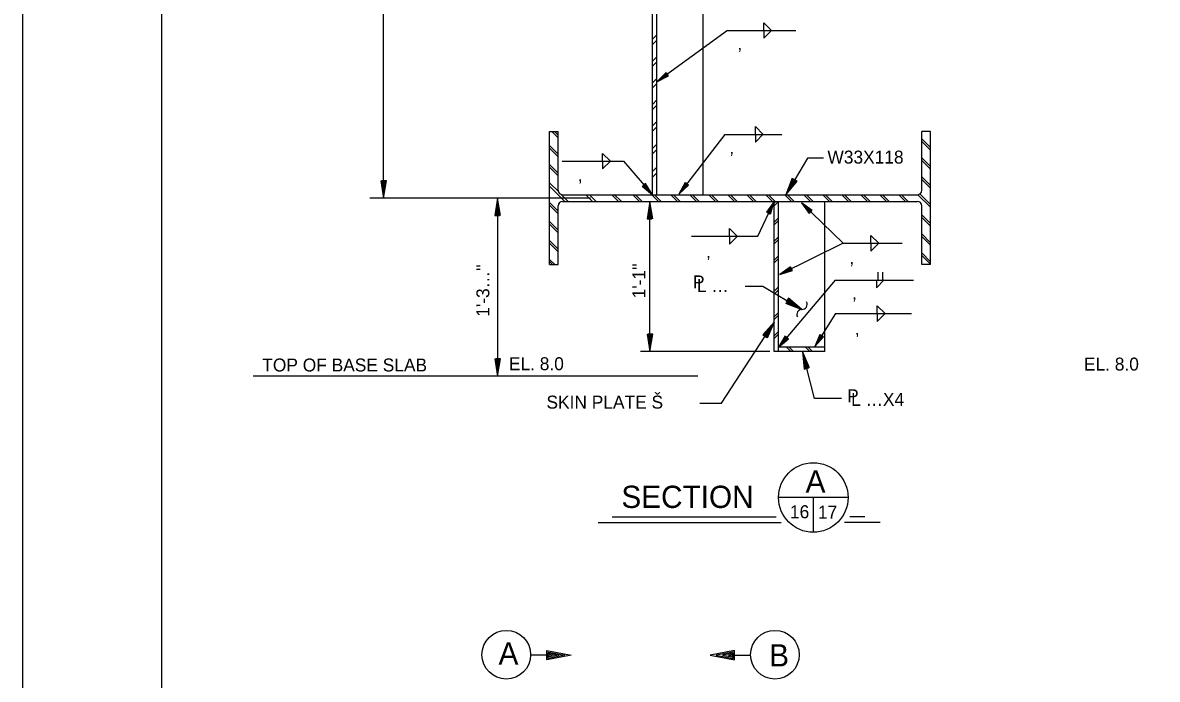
# Model space of a CAD drawing. Extents: x 4.9 to 31.6, y 3.9 to 22.6.
# Drawn here: x 4.91 to 13.07, y 13.34 to 18.06 of the extents above; entities that cross this region are included whole.
import ezdxf

# ---------------------------------------------------------------- set-up
doc = ezdxf.new("R2010")
doc.units = 0
for name, color, linetype in [('Level 1', 7, 'Continuous'), ('Level 10', 7, 'Continuous'), ('Level 2', 7, 'Continuous'), ('Level 25', 7, 'Continuous'), ('Level 3', 7, 'Continuous'), ('Level 44', 7, 'Continuous'), ('Level 50', 7, 'Continuous')]:
    doc.layers.add(name, color=color, linetype=linetype)

msp = doc.modelspace()

# ---------------------------------------------------------------- linework, layer by layer
at = {"layer": 'Level 1'}
for points in [[(4.9069, 22.5927), (31.5735, 22.5927), (31.5735, 3.926), (4.9069, 3.926)], [(5.9069, 22.2594), (31.2402, 22.2594), (31.2402, 4.2594), (5.9069, 4.2594)]]:
    msp.add_lwpolyline(points, close=True, dxfattribs=at)
at = {"layer": 'Level 10'}
for p, q in [((9.4366, 17.9451), (9.4679, 17.9763)), ((9.4366, 17.9074), (9.4679, 17.9386)), ((9.4366, 17.7878), (9.4679, 17.819)), ((9.4366, 17.7501), (9.4679, 17.7813)), ((9.4366, 17.6322), (9.4679, 17.6634)), ((9.4366, 17.5945), (9.4679, 17.6257)), ((9.4366, 17.4766), (9.4679, 17.5079)), ((9.4366, 17.4389), (9.4679, 17.4702)), ((9.4366, 17.3211), (9.4679, 17.3523)), ((9.4366, 17.2834), (9.4679, 17.3146)), ((9.4366, 17.16), (9.4679, 17.1912)), ((9.4366, 17.1208), (9.4679, 17.1521)), ((9.4366, 16.9941), (9.4679, 17.0254)), ((9.4366, 16.9523), (9.4679, 16.9835))]:
    msp.add_line(p, q, dxfattribs=at)
at = {"layer": 'Level 2'}
for p, q in [((9.8012, 16.8271), (9.8012, 20.7144)), ((9.4366, 16.8271), (9.4366, 20.5113)), ((9.4679, 16.8271), (9.4679, 20.5113)), ((8.697, 17.2821), (8.7595, 17.2821)), ((8.697, 16.3238), (8.697, 17.2821)), ((8.7595, 17.2367), (8.7141, 17.2821)), ((8.7595, 17.2555), (8.7329, 17.2821)), ((8.7595, 16.8584), (8.7595, 17.2821)), ((11.4366, 17.2821), (11.3741, 17.2821)), ((11.3741, 16.8584), (11.3741, 17.2821)), ((11.4366, 17.1654), (11.3741, 17.2279)), ((11.4366, 16.3238), (11.4366, 17.2821)), ((8.7595, 17.1188), (8.697, 17.1813)), ((8.7595, 17.0999), (8.697, 17.1624)), ((11.4366, 17.1466), (11.3741, 17.2091)), ((11.4366, 17.0287), (11.3741, 17.0912)), ((11.4366, 17.0099), (11.3741, 17.0724)), ((8.7595, 16.9821), (8.697, 17.0446)), ((8.7595, 16.9632), (8.697, 17.0257)), ((8.761, 16.8488), (8.697, 16.9128)), ((11.4366, 16.8921), (11.3741, 16.9546)), ((11.4366, 16.8732), (11.3741, 16.9357)), ((8.8075, 16.7786), (8.697, 16.889)), ((8.831, 16.7788), (8.7812, 16.8286)), ((8.7908, 16.8271), (11.3429, 16.8271)), ((9.0058, 16.7788), (8.9575, 16.8271)), ((9.0326, 16.7788), (8.9843, 16.8271)), ((9.1932, 16.7788), (9.1449, 16.8271)), ((9.211, 16.7801), (9.1627, 16.8284)), ((9.3437, 16.7788), (9.2954, 16.8271)), ((9.3625, 16.7788), (9.3142, 16.8271)), ((9.4804, 16.7788), (9.4321, 16.8271)), ((9.4993, 16.7788), (9.4509, 16.8271)), ((9.6171, 16.7788), (9.5688, 16.8271)), ((9.636, 16.7788), (9.5876, 16.8271)), ((9.7538, 16.7788), (9.7055, 16.8271)), ((9.7727, 16.7788), (9.7243, 16.8271)), ((9.8905, 16.7788), (9.8422, 16.8271)), ((9.9094, 16.7788), (9.861, 16.8271)), ((10.0272, 16.7788), (9.9789, 16.8271)), ((10.0461, 16.7788), (9.9978, 16.8271)), ((10.1639, 16.7788), (10.1156, 16.8271)), ((10.1828, 16.7788), (10.1345, 16.8271)), ((10.3006, 16.7788), (10.2523, 16.8271)), ((10.3195, 16.7788), (10.2712, 16.8271)), ((10.4374, 16.7788), (10.389, 16.8271)), ((10.4562, 16.7788), (10.4079, 16.8271)), ((10.5741, 16.7788), (10.5257, 16.8271)), ((10.5929, 16.7788), (10.5446, 16.8271)), ((10.7108, 16.7788), (10.6624, 16.8271)), ((10.7296, 16.7788), (10.6813, 16.8271)), ((10.8475, 16.7788), (10.7991, 16.8271)), ((10.8663, 16.7788), (10.818, 16.8271)), ((10.9842, 16.7788), (10.9359, 16.8271)), ((11.003, 16.7788), (10.9547, 16.8271)), ((11.1209, 16.7788), (11.0726, 16.8271)), ((11.1398, 16.7788), (11.0914, 16.8271)), ((11.2576, 16.7788), (11.2093, 16.8271)), ((11.2765, 16.7788), (11.2281, 16.8271)), ((11.4366, 16.7365), (11.346, 16.8271)), ((11.4366, 16.7553), (11.3598, 16.8321)), ((8.7595, 16.7087), (8.697, 16.7712)), ((8.7595, 16.6898), (8.697, 16.7523)), ((8.7595, 16.3238), (8.7595, 16.7475)), ((8.7908, 16.7788), (11.3429, 16.7788)), ((10.3116, 15.6988), (10.3116, 16.7788)), ((10.3429, 15.6988), (10.3429, 16.7788)), ((10.6762, 15.6988), (10.6762, 16.7788)), ((11.3741, 16.3238), (11.3741, 16.7475)), ((11.4366, 16.6186), (11.3741, 16.6811)), ((11.4366, 16.5998), (11.3741, 16.6623)), ((8.7595, 16.572), (8.697, 16.6345)), ((8.7595, 16.5531), (8.697, 16.6156)), ((8.7595, 16.4353), (8.697, 16.4978)), ((11.4366, 16.4819), (11.3741, 16.5444)), ((11.4366, 16.4631), (11.3741, 16.5256)), ((8.7595, 16.4164), (8.697, 16.4789)), ((11.4366, 16.3452), (11.3741, 16.4077)), ((8.7344, 16.3238), (8.697, 16.3612)), ((8.7189, 16.3238), (8.697, 16.3457)), ((8.697, 16.3238), (8.7595, 16.3238)), ((11.4366, 16.3264), (11.3741, 16.3889)), ((11.4366, 16.3238), (11.3741, 16.3238)), ((10.6762, 15.6988), (10.3116, 15.6988)), ((10.6762, 15.73), (10.3429, 15.73)), ((10.4325, 15.6988), (10.4012, 15.73)), ((10.4513, 15.6988), (10.4201, 15.73)), ((10.5692, 15.6988), (10.5379, 15.73)), ((10.5881, 15.6988), (10.5568, 15.73))]:
    msp.add_line(p, q, dxfattribs=at)
at = {"layer": 'Level 25'}
for p, q in [((7.503, 16.803), (7.503, 20.73)), ((10.2386, 18.0629), (10.2945, 18.007)), ((10.2386, 18.0066), (10.2386, 18.0629)), ((9.9777, 18.0072), (9.4679, 17.6389)), ((9.9777, 18.0072), (10.4673, 18.0072)), ((10.2386, 18.0078), (10.2386, 17.9515)), ((10.2386, 17.9515), (10.2945, 18.0074)), ((9.4679, 17.6389), (9.4679, 17.6389)), ((9.4889, 17.6541), (9.4889, 17.6541)), ((10.1774, 17.3166), (10.2333, 17.2607)), ((10.1774, 17.2603), (10.1774, 17.3166)), ((9.9578, 17.2609), (9.6274, 16.8318)), ((9.9578, 17.2609), (10.3683, 17.2609)), ((10.1774, 17.2615), (10.1774, 17.2052)), ((10.1774, 17.2052), (10.2333, 17.2611)), ((8.7879, 17.0687), (9.2284, 17.0687)), ((9.0786, 17.1243), (9.1345, 17.0684)), ((9.0786, 17.0681), (9.0786, 17.1243)), ((9.0786, 17.0692), (9.0786, 17.013)), ((9.0786, 17.013), (9.1345, 17.0689)), ((9.2284, 17.0687), (9.4366, 16.8271)), ((9.4196, 16.8468), (9.4196, 16.8468)), ((9.4366, 16.8271), (9.4366, 16.8271)), ((9.6274, 16.8318), (9.6274, 16.8318)), ((9.6432, 16.8524), (9.6432, 16.8524)), ((8.3232, 16.803), (8.3232, 15.5217)), ((9.4188, 15.6988), (9.4188, 16.7788)), ((10.1956, 16.5276), (10.3116, 16.7788)), ((10.3007, 16.7552), (10.3007, 16.7552)), ((10.3116, 16.7788), (10.3116, 16.7788)), ((10.8079, 16.4774), (10.5084, 16.7685)), ((10.5084, 16.7685), (10.5084, 16.7685)), ((10.527, 16.7504), (10.527, 16.7504)), ((9.9919, 16.5833), (10.0478, 16.5274)), ((9.9919, 16.527), (9.9919, 16.5833)), ((9.717, 16.5276), (10.1956, 16.5276)), ((9.9919, 16.5282), (9.9919, 16.4719)), ((9.9919, 16.4719), (10.0478, 16.5278)), ((11.0091, 16.533), (11.065, 16.4772)), ((11.0091, 16.4768), (11.0091, 16.533)), ((10.8079, 16.4774), (10.3534, 16.2533)), ((10.8079, 16.4774), (11.2334, 16.4774)), ((11.0091, 16.478), (11.0091, 16.4217)), ((11.0091, 16.4217), (11.065, 16.4776)), ((10.3534, 16.2533), (10.3534, 16.2533)), ((10.3767, 16.2648), (10.3767, 16.2648)), ((11.0583, 16.2705), (11.0583, 16.2133)), ((11.092, 16.2697), (11.092, 16.2133)), ((10.7514, 16.2133), (10.3429, 15.73)), ((10.7514, 16.2133), (11.3138, 16.2133)), ((11.0491, 16.2138), (11.0491, 16.1576)), ((11.0491, 16.1576), (11.105, 16.2135)), ((11.0544, 16.0275), (11.1103, 15.9716)), ((11.0544, 15.9712), (11.0544, 16.0275)), ((10.7534, 15.9718), (10.606, 15.7346)), ((10.7534, 15.9718), (11.2996, 15.9718)), ((11.0544, 15.9724), (11.0544, 15.9161)), ((11.0544, 15.9161), (11.1103, 15.972)), ((10.6197, 15.7567), (10.6197, 15.7567)), ((10.2806, 15.6988), (9.3506, 15.6988)), ((10.3429, 15.73), (10.3429, 15.73)), ((10.3596, 15.7499), (10.3596, 15.7499)), ((10.606, 15.7346), (10.606, 15.7346))]:
    msp.add_line(p, q, dxfattribs=at)
for points in [[(9.5346, 17.7062), (9.4679, 17.6389), (9.5527, 17.6811), (9.5372, 17.7026), (9.4889, 17.6541), (9.5466, 17.6828), (9.5366, 17.6966), (9.5092, 17.6688), (9.5404, 17.6845), (9.5363, 17.6902), (9.5303, 17.684)], [(9.3638, 16.8878), (9.4366, 16.8271), (9.3873, 16.9081), (9.3672, 16.8908), (9.4196, 16.8468), (9.3861, 16.9018), (9.3733, 16.8907), (9.4033, 16.8658), (9.385, 16.8955), (9.3797, 16.8909), (9.3863, 16.8854)], [(9.6721, 16.9153), (9.6274, 16.8318), (9.6967, 16.8964), (9.6757, 16.9126), (9.6432, 16.8524), (9.6903, 16.8963), (9.6768, 16.9067), (9.6585, 16.8722), (9.6839, 16.8962), (9.6783, 16.9005), (9.6744, 16.8928)], [(10.2865, 16.6874), (10.3116, 16.7788), (10.2584, 16.7004), (10.2824, 16.6893), (10.3007, 16.7552), (10.2646, 16.7019), (10.28, 16.6948), (10.2902, 16.7325), (10.2708, 16.7035), (10.2771, 16.7005), (10.2793, 16.7089)], [(10.5863, 16.7144), (10.5084, 16.7685), (10.5646, 16.6922), (10.5831, 16.7112), (10.527, 16.7504), (10.5653, 16.6986), (10.5771, 16.7108), (10.545, 16.733), (10.5659, 16.705), (10.5708, 16.71), (10.5636, 16.7148)], [(10.4304, 16.3085), (10.3534, 16.2533), (10.4441, 16.2807), (10.4324, 16.3045), (10.3767, 16.2648), (10.4383, 16.2834), (10.4308, 16.2987), (10.3991, 16.2758), (10.4325, 16.2861), (10.4294, 16.2924), (10.4224, 16.2873)], [(10.3914, 15.8114), (10.3429, 15.73), (10.4151, 15.7914), (10.3948, 15.8085), (10.3596, 15.7499), (10.4087, 15.7916), (10.3957, 15.8026), (10.3758, 15.769), (10.4023, 15.7918), (10.3969, 15.7963), (10.3926, 15.7888)], [(10.6421, 15.8222), (10.606, 15.7346), (10.6685, 15.8058), (10.646, 15.8198), (10.6197, 15.7567), (10.6621, 15.8051), (10.6477, 15.8141), (10.6329, 15.7779), (10.6558, 15.8043), (10.6498, 15.808), (10.6466, 15.8)]]:
    msp.add_lwpolyline(points, dxfattribs=at)
at = {"layer": 'Level 3'}
for p, q in [((10.3116, 16.7736), (10.3168, 16.7788)), ((10.3116, 16.7666), (10.3238, 16.7788)), ((10.3116, 16.7478), (10.3426, 16.7788)), ((10.3116, 16.6299), (10.3429, 16.6612)), ((10.3116, 16.6111), (10.3429, 16.6423)), ((10.3116, 16.4932), (10.3429, 16.5245)), ((10.3116, 16.4744), (10.3429, 16.5056)), ((10.3116, 16.3565), (10.3429, 16.3878)), ((10.3116, 16.3377), (10.3429, 16.3689)), ((10.3116, 16.1343), (10.3429, 16.1655)), ((10.3116, 16.1113), (10.3429, 16.1426)), ((10.3116, 15.949), (10.3429, 15.9802)), ((10.3116, 15.9301), (10.3429, 15.9614)), ((10.2971, 15.884), (10.2971, 15.884)), ((10.3116, 15.8123), (10.3429, 15.8435)), ((10.316, 15.913), (10.316, 15.913)), ((10.3116, 15.7934), (10.3429, 15.8247)), ((10.8441, 14.6494), (10.3441, 14.6494)), ((10.5941, 14.6494), (10.5941, 14.3994)), ((10.5941, 14.6494), (10.5941, 14.3994)), ((9.0466, 14.4686), (10.3639, 14.4686)), ((9.1465, 14.5103), (10.3271, 14.5103)), ((11.0761, 14.4686), (10.8188, 14.4686)), ((10.9636, 14.5103), (10.8576, 14.5103)), ((8.6775, 13.5151), (8.5608, 13.5151)), ((10.0262, 13.5151), (10.1429, 13.5151))]:
    msp.add_line(p, q, dxfattribs=at)
for points in [[(10.6671, 17.0892), (10.5531, 17.0892), (10.3967, 16.8271)], [(10.1028, 16.1703), (10.23, 16.1703), (10.5126, 16.0017)], [(9.7769, 15.3271), (9.933, 15.3271), (10.316, 15.913)], [(10.2651, 15.7973), (10.316, 15.913), (10.2305, 15.82), (10.2601, 15.8006), (10.2971, 15.884), (10.239, 15.8208), (10.258, 15.8084), (10.2788, 15.8561), (10.2475, 15.8216), (10.2553, 15.8165), (10.2598, 15.8271)], [(10.602, 15.3622), (10.5171, 15.6988)], [(10.7973, 15.3622), (10.602, 15.3622)], [(8.6775, 13.5396), (8.6775, 13.5484), (8.8525, 13.5151), (8.6775, 13.4825), (8.6775, 13.5396), (8.8078, 13.5157), (8.6859, 13.4924), (8.6859, 13.5301), (8.7638, 13.5157), (8.6941, 13.5026), (8.6941, 13.5201), (8.7191, 13.5157), (8.7026, 13.5126)], [(10.0262, 13.5396), (10.0262, 13.5484), (9.8512, 13.5151), (10.0262, 13.4825), (10.0262, 13.5396), (9.8959, 13.5157), (10.0178, 13.4924), (10.0178, 13.5301), (9.9399, 13.5157), (10.0096, 13.5026), (10.0096, 13.5201), (9.9845, 13.5157), (10.0011, 13.5126)]]:
    msp.add_lwpolyline(points, dxfattribs=at)
for centre, radius in [((10.5941, 14.6494), 0.25), ((8.3858, 13.5185), 0.175), ((10.3179, 13.5185), 0.175)]:
    msp.add_circle(centre, radius, dxfattribs=at)
at = {"layer": 'Level 44'}
for centre, start, end in [((10.5123, 15.9649), 89.59813, 207.47734), ((10.5129, 16.0384), 269.59813, 27.47734)]:
    msp.add_arc(centre, 0.0368, start, end, dxfattribs=at)
at = {"layer": 'Level 50'}
for p, q in [((7.503, 16.8376), (7.503, 16.8376)), ((10.3967, 16.8271), (10.3967, 16.8271)), ((10.4144, 16.8569), (10.4144, 16.8569)), ((8.991, 16.803), (7.4031, 16.803)), ((7.503, 16.803), (7.503, 16.803)), ((8.3232, 16.803), (8.3232, 16.803)), ((8.3232, 16.7683), (8.3232, 16.7683)), ((9.4188, 16.7788), (9.4188, 16.7788)), ((9.4188, 16.7441), (9.4188, 16.7441)), ((10.4828, 16.0194), (10.4828, 16.0194)), ((10.5126, 16.0017), (10.5126, 16.0017)), ((9.4188, 15.7335), (9.4188, 15.7335)), ((9.4188, 15.6988), (9.4188, 15.6988)), ((10.5171, 15.6988), (10.5171, 15.6988)), ((10.5256, 15.6652), (10.5256, 15.6652)), ((9.764, 15.5217), (6.5657, 15.5217)), ((8.3232, 15.5564), (8.3232, 15.5564)), ((8.3232, 15.5217), (8.3232, 15.5217))]:
    msp.add_line(p, q, dxfattribs=at)
for points in [[(7.4823, 16.9276), (7.503, 16.803), (7.5236, 16.9276), (7.4883, 16.9276), (7.503, 16.8376), (7.517, 16.9223), (7.4943, 16.9223), (7.503, 16.871), (7.5103, 16.917), (7.501, 16.917), (7.503, 16.9056)], [(10.4428, 16.9448), (10.3967, 16.8271), (10.4783, 16.9236), (10.448, 16.9417), (10.4144, 16.8569), (10.4699, 16.9224), (10.4504, 16.934), (10.4315, 16.8855), (10.4614, 16.9213), (10.4534, 16.926), (10.4493, 16.9153)], [(8.3439, 16.6783), (8.3232, 16.803), (8.3025, 16.6783), (8.3379, 16.6783), (8.3232, 16.7683), (8.3092, 16.6836), (8.3319, 16.6836), (8.3232, 16.735), (8.3159, 16.689), (8.3252, 16.689), (8.3232, 16.7003)], [(9.4395, 16.6541), (9.4188, 16.7788), (9.3982, 16.6541), (9.4335, 16.6541), (9.4188, 16.7441), (9.4048, 16.6595), (9.4275, 16.6595), (9.4188, 16.7108), (9.4115, 16.6648), (9.4208, 16.6648), (9.4188, 16.6761)], [(10.3949, 16.0478), (10.5126, 16.0017), (10.4161, 16.0833), (10.398, 16.0529), (10.4828, 16.0194), (10.4173, 16.0748), (10.4057, 16.0554), (10.4542, 16.0365), (10.4185, 16.0664), (10.4137, 16.0584), (10.4244, 16.0543)], [(9.3982, 15.8235), (9.4188, 15.6988), (9.4395, 15.8235), (9.4042, 15.8235), (9.4188, 15.7335), (9.4328, 15.8181), (9.4102, 15.8181), (9.4188, 15.7668), (9.4262, 15.8128), (9.4168, 15.8128), (9.4188, 15.8015)], [(10.5677, 15.583), (10.5171, 15.6988), (10.5276, 15.5729), (10.5619, 15.5815), (10.5256, 15.6652), (10.5328, 15.5797), (10.5547, 15.5852), (10.5338, 15.6329), (10.5379, 15.5865), (10.547, 15.5887), (10.5423, 15.5992)], [(8.3025, 15.6464), (8.3232, 15.5217), (8.3439, 15.6464), (8.3085, 15.6464), (8.3232, 15.5564), (8.3372, 15.641), (8.3145, 15.641), (8.3232, 15.5897), (8.3305, 15.6357), (8.3212, 15.6357), (8.3232, 15.6244)]]:
    msp.add_lwpolyline(points, dxfattribs=at)
for centre, start, end in [((8.7908, 16.8584), 180, 270), ((11.3429, 16.8584), 270, 0), ((8.7908, 16.7475), 90, 180), ((11.3429, 16.7475), 0, 90)]:
    msp.add_arc(centre, 0.0313, start, end, dxfattribs=at)

# ---------------------------------------------------------------- texts
at = {"layer": 'Level 25'}
for s, height, p in [('‚', 0.0933, (10.051, 17.8696)), ('W33X118', 0.09329, (10.6957, 17.0507)), ('‚', 0.0933, (9.993, 17.1221)), ('‚', 0.0933, (8.9037, 16.9238)), ('‚', 0.0933, (9.8257, 16.3739)), ('‚', 0.0933, (10.8568, 16.3297)), ('P', 0.0933, (9.7283, 16.1526)), ('L …', 0.09329, (9.7566, 16.1268)), ('‚', 0.0933, (10.876, 16.0756)), ('‚', 0.0933, (10.8963, 15.8197)), ('TOP OF BASE SLAB', 0.093292, (6.6303, 15.5555)), (' EL. 8.0', 0.09329, (8.3697, 15.5648)), ('             EL. 8.0', 0.093292, (12.0902, 15.5621)), ('P', 0.0933, (10.8375, 15.3337)), ('SKIN PLATE Š', 0.093292, (8.6746, 15.2885)), ('L …X4', 0.09329, (10.8661, 15.3085))]:
    msp.add_text(s, height=height, dxfattribs=at).set_placement(p)
for s, p in [("1'-1''", (9.3863, 16.0813)), ("1'-3…''", (8.2638, 15.9493))]:
    msp.add_text(s, height=0.09329, rotation=90, dxfattribs=at).set_placement(p)
at = {"layer": 'Level 3'}
for s, height, p in [('A', 0.16, (10.5389, 14.6851)), ('SECTION', 0.16, (9.2136, 14.5742)), ('16', 0.09358, (10.4258, 14.5)), ('17', 0.09358, (10.6271, 14.4976))]:
    msp.add_text(s, height=height, dxfattribs=at).set_placement(p)
at = {"layer": 'Level 50'}
for s, p in [('A', (8.33, 13.4477)), ('B', (10.2768, 13.4343))]:
    msp.add_text(s, height=0.16, dxfattribs=at).set_placement(p)

doc.saveas('drawing.dxf')
